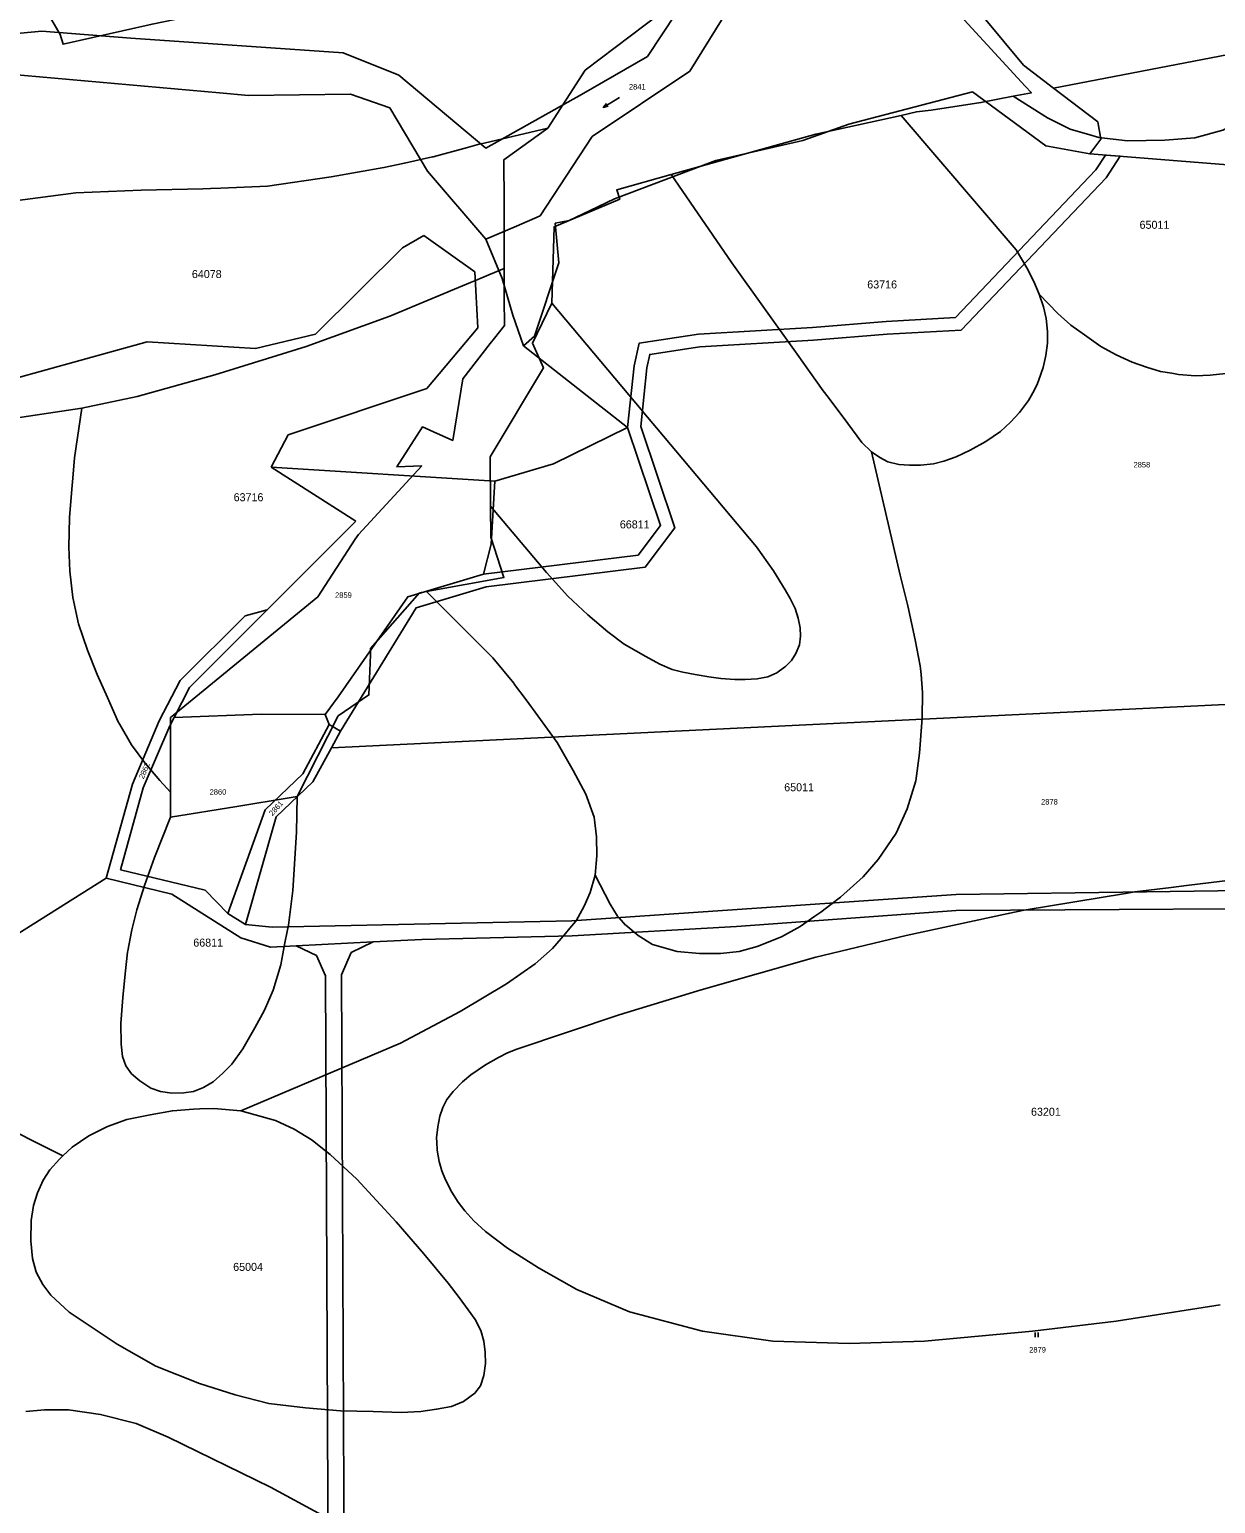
# Model space of a CAD drawing. Extents: x -546762 to -540209, y -1046851 to -1035694.
# Drawn here: x -543066.9 to -542696.6, y -1038969.2 to -1038508.7 of the extents above; entities that cross this region are included whole.
import ezdxf

# ---------------------------------------------------------------- set-up
doc = ezdxf.new("R2010")
doc.units = 0
for name, color, linetype in [('Vrstva 1', 7, 'Continuous'), ('Vrstva 18', 7, 'Continuous'), ('Vrstva 25', 7, 'Continuous'), ('Vrstva 30', 7, 'Continuous'), ('Vrstva 52', 7, 'Continuous'), ('Vrstva 53', 7, 'Continuous')]:
    doc.layers.add(name, color=color, linetype=linetype)

msp = doc.modelspace()

# ---------------------------------------------------------------- linework, layer by layer
at = {"layer": 'Vrstva 1'}
for points in [[(-542842.25, -1038469.03), (-542873.94, -1038517.13)], [(-542860.79, -1038521.73), (-542832.95, -1038476.83)], [(-542756.55, -1038519.9), (-542775.06, -1038497.57)], [(-543063.13, -1038509.26), (-543078.75, -1038510.74)], [(-543035.35, -1038511.41), (-543063.13, -1038509.26)], [(-542969.05, -1038515.97), (-543035.35, -1038511.41)], [(-542951.64, -1038523.04), (-542969.05, -1038515.97)], [(-542873.94, -1038517.13), (-542894.61, -1038529.01)], [(-542692.62, -1038516.57), (-542747.19, -1038527.04)], [(-543077.99, -1038522.23), (-543007.63, -1038528.5)], [(-542891.3, -1038542.14), (-542860.79, -1038521.73)], [(-542747.19, -1038527.04), (-542756.55, -1038519.9)], [(-542924.44, -1038545.8), (-542951.64, -1038523.04)], [(-542733.35, -1038537.59), (-542747.19, -1038527.04)], [(-543007.63, -1038528.5), (-542998.62, -1038529.3)], [(-542998.62, -1038529.3), (-542966.75, -1038528.96)], [(-542966.75, -1038528.96), (-542954.4, -1038533.23)], [(-542894.61, -1038529.01), (-542924.44, -1038545.8)], [(-542772.48, -1038528.16), (-542811.15, -1038538.33)], [(-542749.64, -1038545.08), (-542772.48, -1038528.16)], [(-542954.4, -1038533.23), (-542942.65, -1038552.99)], [(-542811.15, -1038538.33), (-542825.48, -1038543.45)], [(-542732.43, -1038542.98), (-542733.35, -1038537.59)], [(-542907.51, -1038566.97), (-542891.3, -1038542.14)], [(-542825.48, -1038543.45), (-542852.64, -1038549.62)], [(-542735.84, -1038547.59), (-542749.64, -1038545.08)], [(-542735.84, -1038547.59), (-542732.43, -1038542.98)], [(-542852.64, -1038549.62), (-542884.34, -1038561.63)], [(-542591.23, -1038559.12), (-542735.84, -1038547.59)], [(-542942.65, -1038552.99), (-542924.51, -1038574.26)], [(-542884.34, -1038561.63), (-542891.89, -1038565.25)], [(-542914.92, -1038570.15), (-542907.51, -1038566.97)], [(-542898.42, -1038568.39), (-542902.77, -1038569.21)], [(-542891.89, -1038565.25), (-542898.42, -1038568.39)], [(-542950.49, -1038576.9), (-542943.85, -1038573.09)], [(-542943.85, -1038573.09), (-542927.94, -1038584.41)], [(-542924.51, -1038574.26), (-542914.92, -1038570.15)], [(-542902.77, -1038569.21), (-542901.69, -1038581.56)], [(-542977.68, -1038603.87), (-542950.49, -1038576.9)], [(-542924.51, -1038574.26), (-542919.35, -1038586.46)], [(-542901.69, -1038581.56), (-542909.31, -1038604.56)], [(-542927.94, -1038584.41), (-542926.95, -1038601.94)], [(-542919.35, -1038586.46), (-542916.05, -1038597.96)], [(-542916.05, -1038597.96), (-542912.71, -1038607.56)], [(-542996.42, -1038608.34), (-542977.68, -1038603.87)], [(-542926.95, -1038601.94), (-542942.92, -1038620.89)], [(-542909.31, -1038604.56), (-542912.71, -1038607.56)], [(-543072.25, -1038617.91), (-543030.16, -1038606.32)], [(-543030.16, -1038606.32), (-542996.42, -1038608.34)], [(-542912.71, -1038607.56), (-542880.24, -1038633)], [(-542942.92, -1038620.89), (-542986.21, -1038635.36)], [(-542986.21, -1038635.36), (-542991.51, -1038645.44)], [(-542880.24, -1038633), (-542903.35, -1038644.43)], [(-542991.51, -1038645.44), (-542921.61, -1038649.84)], [(-542965.06, -1038662.35), (-542991.51, -1038645.44)], [(-542903.35, -1038644.43), (-542921.61, -1038649.84)], [(-542921.61, -1038649.84), (-542922.85, -1038669.54)], [(-542992.71, -1038690.02), (-542965.06, -1038662.35)], [(-542922.85, -1038669.54), (-542925.17, -1038678.84)], [(-542925.17, -1038678.84), (-542948.84, -1038685.99)], [(-542948.84, -1038685.99), (-542970.52, -1038717.21)], [(-542999.62, -1038691.84), (-543019.88, -1038712.12)], [(-543016.94, -1038714.27), (-542992.71, -1038690.02)], [(-542992.71, -1038690.02), (-542999.62, -1038691.84)], [(-543019.88, -1038712.12), (-543026.41, -1038724.65)], [(-543021.82, -1038723.63), (-543016.94, -1038714.27)], [(-542970.52, -1038717.21), (-542974.62, -1038722.72)], [(-542828.82, -1038726.12), (-542684.94, -1038719.14)], [(-543026.41, -1038724.65), (-543034.82, -1038744.43)], [(-543023.15, -1038726.19), (-543021.82, -1038723.63)], [(-542994.61, -1038722.57), (-543021.82, -1038723.63)], [(-542974.62, -1038722.72), (-542994.61, -1038722.57)], [(-542974.62, -1038722.72), (-542973.33, -1038725.86)], [(-543031.42, -1038745.62), (-543023.15, -1038726.19)], [(-542973.33, -1038725.86), (-542981.65, -1038741.23)], [(-542973.33, -1038725.86), (-542969.86, -1038727.86)], [(-542972.7, -1038733.09), (-542828.82, -1038726.12)], [(-542969.86, -1038727.86), (-542972.7, -1038733.09)], [(-542978.43, -1038743.69), (-542972.7, -1038733.09)], [(-542981.65, -1038741.23), (-542993.36, -1038752.43)], [(-543034.82, -1038744.43), (-543043.01, -1038773.83)], [(-543038.54, -1038771.21), (-543031.42, -1038745.62)], [(-542989.91, -1038754.67), (-542978.43, -1038743.69)], [(-542993.36, -1038752.43), (-543004.98, -1038784.89)], [(-542999.54, -1038788.34), (-542989.91, -1038754.67)], [(-543043.01, -1038773.83), (-543147.51, -1038839.62)], [(-543043.01, -1038773.83), (-543022.5, -1038778.8)], [(-543012.11, -1038777.61), (-543038.54, -1038771.21)], [(-543022.5, -1038778.8), (-543000.96, -1038792.46)], [(-543004.98, -1038784.89), (-543012.11, -1038777.61)], [(-542777.63, -1038778.9), (-542897.65, -1038787.11)], [(-542658.71, -1038777.28), (-542777.63, -1038778.9)], [(-543004.98, -1038784.89), (-542999.54, -1038788.34)], [(-542777.62, -1038783.93), (-542846.15, -1038788.93)], [(-542641.97, -1038783.05), (-542777.62, -1038783.93)], [(-542991.17, -1038789.16), (-542999.54, -1038788.34)], [(-542897.65, -1038787.11), (-542991.17, -1038789.16)], [(-542846.15, -1038788.93), (-542897.46, -1038791.79)], [(-543000.96, -1038792.46), (-542991.67, -1038795.33)], [(-542959.67, -1038793.75), (-542983.67, -1038794.94)], [(-542959.67, -1038793.75), (-542966.52, -1038797)], [(-542944.46, -1038792.99), (-542959.67, -1038793.75)], [(-542897.46, -1038791.79), (-542944.46, -1038792.99)], [(-542991.67, -1038795.33), (-542983.67, -1038794.94)], [(-542983.67, -1038794.94), (-542977.34, -1038797.94)], [(-542977.34, -1038797.94), (-542974.55, -1038804.33)], [(-542966.52, -1038797), (-542969.58, -1038804.02)], [(-542974.55, -1038804.33), (-542973.68, -1038990.32)], [(-542969.58, -1038804.02), (-542968.71, -1038988.93)]]:
    msp.add_lwpolyline(points, dxfattribs=at)
at = {"layer": 'Vrstva 25'}
for p, q in [((-542752.96, -1038917.23), (-542752.96, -1038915.73)), ((-542751.96, -1038917.23), (-542751.96, -1038915.73))]:
    msp.add_line(p, q, dxfattribs=at)
for points in [[(-542882.68, -1038529.97), (-542887.82, -1038533.05), (-542886.28, -1038532.71)], [(-542887.82, -1038533.05), (-542886.79, -1038531.85)]]:
    msp.add_lwpolyline(points, dxfattribs=at)
at = {"layer": 'Vrstva 30'}
msp.add_lwpolyline([(-542925.17, -1038678.84), (-542876.87, -1038672.91), (-542869.92, -1038663.65), (-542880.24, -1038633), (-542878.16, -1038613.78), (-542876.56, -1038606.7), (-542858.08, -1038603.86), (-542822.48, -1038601.79), (-542799.45, -1038599.92), (-542777.86, -1038598.72), (-542733.96, -1038552.59), (-542730.97, -1038547.98), (-542726.43, -1038548.34), (-542730.81, -1038555.08), (-542776.06, -1038602.63), (-542799.18, -1038603.91), (-542822.2, -1038605.78), (-542857.66, -1038607.84), (-542873.26, -1038610.24), (-542874.21, -1038614.43), (-542876.11, -1038632.73), (-542865.46, -1038664.37), (-542874.69, -1038676.67), (-542924.34, -1038682.77), (-542946.23, -1038689.38), (-542969.86, -1038727.86), (-542973.33, -1038725.86), (-542974.62, -1038722.72), (-542970.52, -1038717.21), (-542948.84, -1038685.99), (-542925.17, -1038678.84)], dxfattribs=at)
at = {"layer": 'Vrstva 52'}
for points in [[(-542687.72, -1038415.16), (-542698.94, -1038420.48), (-542725.54, -1038435.79), (-542740.92, -1038453.31), (-542741.35, -1038454.19), (-542747.57, -1038466.86), (-542771.63, -1038475.16), (-542776.28, -1038504.44), (-542756.08, -1038526.38), (-542754.14, -1038528.49), (-542759.81, -1038529.6)], [(-542912.45, -1038432.16), (-542946.17, -1038466.68), (-542990.21, -1038499.06), (-543028.67, -1038507.04), (-543056.48, -1038513.32), (-543057.35, -1038510.27), (-543067.77, -1038492.27), (-543090.66, -1038481.63), (-543127.25, -1038484.21), (-543150.42, -1038511.38), (-543175.81, -1038521.33), (-543188.66, -1038530.47), (-543186.57, -1038531.98), (-543161.63, -1038550.02), (-543154.1, -1038555.47), (-543148.54, -1038559.49), (-543141.66, -1038560.78), (-543100.26, -1038568.53)], [(-542905.15, -1038539.57), (-542893.48, -1038521.45), (-542865.34, -1038500.14)], [(-542669.21, -1038517.65), (-542669.9, -1038519.08), (-542674.51, -1038526), (-542678.1, -1038530.45), (-542678.85, -1038531.38), (-542685.72, -1038536.16), (-542694.38, -1038540.2), (-542703.04, -1038542.59), (-542712.45, -1038543.34)], [(-542759.81, -1038529.6), (-542769.89, -1038531.58), (-542785.37, -1038533.88), (-542790, -1038534.49), (-542794.81, -1038535.56)], [(-542712.45, -1038543.34), (-542724.11, -1038543.49), (-542733.07, -1038542.44), (-542735.83, -1038541.66), (-542742.03, -1038539.9), (-542749.05, -1038536.31), (-542759.81, -1038529.6)], [(-542794.81, -1038535.56), (-542821.42, -1038541.45), (-542866.55, -1038554.05)], [(-542794.81, -1038535.56), (-542758.92, -1038577.54), (-542755.51, -1038583.18), (-542753.38, -1038587.45), (-542751.67, -1038591.38)], [(-542905.15, -1038539.57), (-542924.97, -1038544.19), (-542926.51, -1038544.55), (-542930.2, -1038545.56), (-542940.88, -1038548.47), (-542941.1, -1038548.52), (-542949.87, -1038550.45), (-542956.31, -1038551.87), (-542972.77, -1038554.75), (-542992.64, -1038557.63), (-543007.21, -1038558.27), (-543010.41, -1038558.41), (-543012.8, -1038558.47), (-543032.11, -1038558.94), (-543052.5, -1038559.72), (-543076.29, -1038562.86), (-543100.26, -1038568.53)], [(-542918.72, -1038583.34), (-542918.78, -1038562.52), (-542918.79, -1038559.86), (-542918.81, -1038552.5), (-542918.82, -1038549.39), (-542905.15, -1038539.57)], [(-542866.55, -1038554.05), (-542883.59, -1038558.81), (-542882.65, -1038561.77), (-542903.14, -1038570.36), (-542903.85, -1038594.25)], [(-542804.06, -1038640.68), (-542807.04, -1038637.69), (-542812.85, -1038629.83), (-542814.55, -1038627.6), (-542817.62, -1038623.57), (-542819.12, -1038621.61), (-542827.22, -1038610.1), (-542847.61, -1038581.59), (-542866.55, -1038554.05)], [(-543009.06, -1038616.59), (-542980.57, -1038607.7), (-542954.43, -1038598.28), (-542929.25, -1038587.75), (-542927.72, -1038587.11), (-542923.49, -1038585.34), (-542918.72, -1038583.34)], [(-542931.67, -1038617.81), (-542923.11, -1038606.84), (-542921.78, -1038605.14), (-542918.66, -1038601.14), (-542918.69, -1038592.89), (-542918.72, -1038583.34)], [(-542751.67, -1038591.38), (-542750.3, -1038595.31), (-542749.54, -1038598.98), (-542749.11, -1038603.08), (-542749.11, -1038606.66), (-542749.62, -1038610.59), (-542750.47, -1038614.35), (-542751.75, -1038618.19), (-542752.24, -1038619.29), (-542753.12, -1038621.27), (-542754.19, -1038623.17), (-542755, -1038624.6), (-542757.81, -1038628.36), (-542760.63, -1038631.35), (-542763.79, -1038634.33), (-542768.38, -1038637.43), (-542773.24, -1038640.08), (-542777.6, -1038642.21), (-542781.44, -1038643.58), (-542784.68, -1038644.35), (-542788.78, -1038644.86)], [(-542751.67, -1038591.38), (-542745.86, -1038597.49), (-542741.76, -1038601.08), (-542737.58, -1038604.06), (-542732.46, -1038607.74), (-542727.68, -1038610.38), (-542722.64, -1038612.6), (-542718.21, -1038614.23), (-542713.77, -1038615.51), (-542710.24, -1038616.11), (-542708.22, -1038616.45), (-542702.84, -1038616.96), (-542698.32, -1038616.7), (-542693.37, -1038616.19)], [(-542903.85, -1038594.25), (-542909.92, -1038606.66), (-542906.49, -1038614.46), (-542923.12, -1038642.19), (-542922.97, -1038657.63)], [(-542843.54, -1038711.78), (-542839.79, -1038711.52), (-542836.46, -1038710.92), (-542833.64, -1038709.64), (-542831.17, -1038707.93), (-542830.9, -1038707.67), (-542829.03, -1038705.8), (-542827.67, -1038703.66), (-542826.56, -1038700.93), (-542826.22, -1038698.28), (-542826.3, -1038695.64), (-542826.9, -1038692.56), (-542827.92, -1038689.57), (-542829.46, -1038686.5), (-542831, -1038683.77), (-542834.67, -1038677.79), (-542839.96, -1038670.36), (-542871.17, -1038633.19), (-542875.17, -1038628.42), (-542875.48, -1038628.05), (-542903.85, -1038594.25)], [(-543050.62, -1038627.05), (-543033.37, -1038623.39), (-543009.06, -1038616.59)], [(-543022.91, -1038747.01), (-543022.89, -1038723.64), (-543021.87, -1038722.8), (-543013.9, -1038716.29), (-542976.88, -1038685.99), (-542965.23, -1038667.93), (-542964.25, -1038666.42), (-542944.49, -1038645.07), (-542947.05, -1038645.16), (-542952.24, -1038645.34), (-542944.24, -1038632.88), (-542940.77, -1038634.41), (-542934.77, -1038637.06), (-542931.67, -1038617.81)], [(-543084.03, -1038631.99), (-543050.62, -1038627.05)], [(-543050.62, -1038627.05), (-543052.87, -1038642.48), (-543053.45, -1038648.85)], [(-542788.57, -1038710.23), (-542788.72, -1038708.35), (-542788.88, -1038707.5), (-542790.36, -1038699.38), (-542792.75, -1038688.77), (-542795.14, -1038679.21), (-542804.06, -1038640.68)], [(-542788.78, -1038644.86), (-542792.19, -1038644.86), (-542795.52, -1038644.6), (-542798.93, -1038643.75), (-542801.41, -1038642.47), (-542804.06, -1038640.68)], [(-543053.45, -1038648.85), (-543053.76, -1038652.34), (-543054.51, -1038661.16), (-543054.66, -1038670.43), (-543054.36, -1038677.9), (-543053.46, -1038686.12), (-543051.67, -1038694.34), (-543048.83, -1038702.56), (-543045.85, -1038710.18), (-543042.56, -1038717.35), (-543041.09, -1038720.75), (-543039.27, -1038724.97), (-543038.78, -1038725.82), (-543035.09, -1038732.15), (-543030.91, -1038737.83), (-543026.28, -1038743.36), (-543022.91, -1038747.01)], [(-542922.97, -1038657.63), (-542922.88, -1038667.27), (-542918.83, -1038679.92), (-542942.98, -1038684.29)], [(-542922.97, -1038657.63), (-542905.57, -1038678.39), (-542898.85, -1038685.73), (-542892.62, -1038691.54), (-542886.39, -1038696.83), (-542881.27, -1038700.68), (-542874.53, -1038704.6), (-542870.09, -1038706.99), (-542866.33, -1038708.62), (-542862.92, -1038709.47), (-542859.08, -1038710.24), (-542854.81, -1038710.92), (-542851.14, -1038711.44), (-542846.7, -1038711.78), (-542843.54, -1038711.78)], [(-542942.98, -1038684.29), (-542945.15, -1038684.68), (-542960.45, -1038702.08), (-542960.52, -1038704.02), (-542960.95, -1038716.6), (-542970.59, -1038723.14), (-542983.41, -1038748.35)], [(-542942.98, -1038684.29), (-542922.32, -1038705.02), (-542915.75, -1038712.94), (-542915.5, -1038713.29), (-542911.92, -1038718.14), (-542908.28, -1038723.1), (-542902.16, -1038731.47), (-542897.23, -1038740.14), (-542893.2, -1038747.61), (-542890.66, -1038754.78), (-542889.91, -1038760.91), (-542889.76, -1038766.89), (-542890.36, -1038772.87)], [(-542890.36, -1038772.87), (-542885.62, -1038781.92), (-542883.32, -1038785.68), (-542882.82, -1038786.25), (-542880.85, -1038788.5), (-542880.78, -1038788.55), (-542876.92, -1038791.74), (-542872.4, -1038794.56), (-542864.71, -1038796.78), (-542857.8, -1038797.38), (-542851.23, -1038797.38), (-542845.34, -1038796.7), (-542839.7, -1038795.16), (-542832.19, -1038792.17), (-542826.3, -1038788.93), (-542821.74, -1038785.74), (-542819.82, -1038784.4), (-542816.71, -1038782.04), (-542813.76, -1038779.79), (-542806.64, -1038773.36), (-542802.01, -1038767.98), (-542796.33, -1038759.76), (-542792.9, -1038752.14), (-542790.21, -1038743.47), (-542789.02, -1038734.8), (-542788.27, -1038723.89), (-542788.12, -1038715.82), (-542788.57, -1038710.23)], [(-543022.92, -1038754.73), (-543022.91, -1038747.01)], [(-542983.41, -1038748.35), (-542985.92, -1038748.76), (-543002.23, -1038751.39), (-543022.92, -1038754.73)], [(-543018.74, -1038840.92), (-543015.76, -1038840.41), (-543012.6, -1038839.21), (-543012.12, -1038838.92), (-543009.61, -1038837.42), (-543006.54, -1038834.77), (-543003.81, -1038831.95), (-543000.31, -1038827.17), (-542996.55, -1038820.6), (-542993.59, -1038815.07), (-542990.9, -1038808.79), (-542988.51, -1038800.87), (-542987.18, -1038793.98), (-542986.51, -1038790.51), (-542986.12, -1038788.46), (-542984.77, -1038777.7), (-542983.58, -1038759.47), (-542983.41, -1038748.35)], [(-543022.92, -1038754.73), (-543027.97, -1038767.37), (-543031.02, -1038776.08), (-543033.41, -1038783.68), (-543035.03, -1038789.92), (-543035.13, -1038790.48), (-543036.24, -1038796.55), (-543036.31, -1038796.92), (-543037.08, -1038803.67), (-543037.76, -1038811.1), (-543038.44, -1038819.21), (-543038.29, -1038825.63), (-543037.86, -1038829.56), (-543036.92, -1038832.47), (-543035.05, -1038834.94), (-543032.49, -1038837.08), (-543029.07, -1038839.47), (-543026, -1038840.49), (-543022.5, -1038841.01), (-543018.74, -1038840.92)], [(-542890.36, -1038772.87), (-542891.85, -1038778.25), (-542893.79, -1038782.58), (-542896.27, -1038787.1), (-542896.33, -1038787.21), (-542898.2, -1038789.44), (-542899.63, -1038791.15), (-542903.66, -1038795.79), (-542909.04, -1038800.57), (-542918, -1038806.85), (-542932.49, -1038815.51), (-542951.16, -1038825.38), (-543000.99, -1038846.45)], [(-542793.19, -1038791.68), (-542761.35, -1038784.9), (-542756.34, -1038783.83), (-542724.75, -1038778.57), (-542721.83, -1038778.08), (-542710.49, -1038776.72), (-542705.69, -1038776.14), (-542687.64, -1038773.96)], [(-542787.53, -1038918.44), (-542811.05, -1038919.22), (-542834.84, -1038918.44), (-542856.8, -1038915.3), (-542879.61, -1038909.29), (-542896.04, -1038902.26), (-542907.99, -1038895.54), (-542917.7, -1038889.41), (-542924.57, -1038884.18), (-542928.24, -1038880.91), (-542930.97, -1038877.75), (-542933.11, -1038875.02), (-542935.07, -1038871.86), (-542937.03, -1038868.1), (-542938.23, -1038865.2), (-542939.08, -1038862.3), (-542939.68, -1038858.79), (-542939.79, -1038856.31), (-542939.85, -1038854.95), (-542939.42, -1038851.45), (-542938.83, -1038848.12), (-542937.89, -1038845.47), (-542936.62, -1038842.96), (-542934.62, -1038840.47), (-542931.79, -1038837.49), (-542929.11, -1038835.3), (-542924.57, -1038832.17), (-542920.52, -1038829.83), (-542917.7, -1038828.42), (-542914.74, -1038827.25), (-542882.85, -1038816.52), (-542857.23, -1038808.68), (-542821.42, -1038798.48), (-542793.19, -1038791.68)], [(-543056.55, -1038860.56), (-543079.66, -1038848.97), (-543088.71, -1038845.38), (-543095.8, -1038843.33), (-543100.4, -1038842.65), (-543106.55, -1038842.14), (-543111.84, -1038842.39), (-543116.96, -1038842.99), (-543122.51, -1038844.18), (-543131.79, -1038847), (-543142.4, -1038850.44), (-543151.96, -1038852.83), (-543159.1, -1038853.91)], [(-543000.99, -1038846.45), (-543009.42, -1038845.8), (-543013.76, -1038845.92), (-543015.73, -1038845.97), (-543022.31, -1038846.48), (-543029.3, -1038847.76), (-543036.56, -1038849.21), (-543042.62, -1038851.35), (-543048.42, -1038854.34), (-543053.63, -1038857.84), (-543056.55, -1038860.56)], [(-542944.79, -1038940.46), (-542939.84, -1038939.69), (-542935.14, -1038938.84), (-542931.39, -1038937.3), (-542927.89, -1038934.74), (-542926.09, -1038932.35), (-542925.07, -1038929.19), (-542924.56, -1038925.43), (-542924.64, -1038921.84), (-542925.07, -1038918.43), (-542926.01, -1038915.1), (-542927.8, -1038911.68), (-542929.94, -1038908.61), (-542932.84, -1038904.85), (-542936.2, -1038900.34), (-542943.8, -1038891.12), (-542952.51, -1038881.21), (-542964.71, -1038867.89), (-542973.08, -1038860.12), (-542975.98, -1038857.84), (-542978.71, -1038855.68), (-542984.26, -1038852.26), (-542990.15, -1038849.53), (-543000.99, -1038846.45)], [(-543056.55, -1038860.56), (-543057.3, -1038861.26), (-543057.63, -1038861.62), (-543060.63, -1038864.93), (-543062.68, -1038868.17), (-543064.47, -1038872.1), (-543065.66, -1038876.03), (-543066.39, -1038880.71), (-543066.56, -1038887.11), (-543066.05, -1038892.66), (-543064.85, -1038896.93), (-543062.81, -1038900.77), (-543060.33, -1038904.1), (-543054.52, -1038909.37), (-543039.59, -1038919.38), (-543027.49, -1038926.26), (-543013.9, -1038931.64), (-543002.69, -1038935.22), (-542992.24, -1038937.91), (-542980.74, -1038939.26), (-542969.83, -1038940.16), (-542959.68, -1038940.46), (-542950.93, -1038940.72), (-542944.79, -1038940.46)], [(-542695.14, -1038907.14), (-542727.67, -1038912.16), (-542753.81, -1038915.3), (-542787.53, -1038918.44)], [(-542975.59, -1038972.75), (-542991.72, -1038964.08), (-543023.69, -1038948.39), (-543033.69, -1038944.2), (-543044.75, -1038941.36), (-543054.75, -1038939.87), (-543062.22, -1038939.87), (-543068.05, -1038940.46)]]:
    msp.add_lwpolyline(points, dxfattribs=at)

# ---------------------------------------------------------------- texts
at = {"layer": 'Vrstva 18'}
for s, p in [('2841', (-542879.79, -1038527.47)), ('2858', (-542722.23, -1038645.52)), ('2859', (-542971.55, -1038686.25)), ('2860', (-543010.71, -1038747.73)), ('2878', (-542751.1, -1038750.82)), ('2879', (-542754.81, -1038921.99))]:
    msp.add_text(s, height=1.7, dxfattribs=at).set_placement(p)
for s, rotation, p in [('2862', 67.3119, (-543031.31, -1038742.97)), ('2861', 48.4043, (-542991.09, -1038754.51))]:
    msp.add_text(s, height=1.7, rotation=rotation, dxfattribs=at).set_placement(p)
at = {"layer": 'Vrstva 53'}
for s, p in [('65011', (-542720.34, -1038570.98)), ('64078', (-543016.25, -1038586.37)), ('63716', (-542805.37, -1038589.61)), ('63716', (-543003.21, -1038656.08)), ('66811', (-542882.62, -1038664.57)), ('65011', (-542831.3, -1038746.67)), ('66811', (-543015.81, -1038795.2)), ('63201', (-542754.24, -1038848.04)), ('65004', (-543003.35, -1038896.5))]:
    msp.add_text(s, height=2.5, dxfattribs=at).set_placement(p)

doc.saveas('drawing.dxf')
